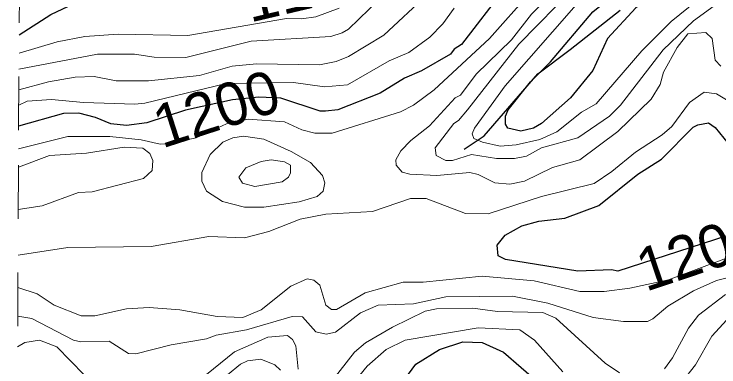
# Model space of a CAD drawing. Extents: x 577 to 602.9, y 7483.8 to 7511.6.
# Drawn here: x 577.007 to 578.319, y 7485.181 to 7485.838 of the extents above; entities that cross this region are included whole.
import ezdxf
from ezdxf.enums import TextEntityAlignment as Align

# ---------------------------------------------------------------- set-up
doc = ezdxf.new("R2010")
doc.units = 0
doc.header["$LTSCALE"] = 0.032
doc.linetypes.add('SHORT_DASHED', pattern=[2.7, 1.5, -1.2])
for name, color, linetype, lineweight in [('1', 7, 'Continuous', 25), ('2', 7, 'Continuous', 13), ('26', 7, 'Continuous', 25), ('62', 7, 'SHORT_DASHED', 13)]:
    doc.layers.add(name, color=color, linetype=linetype, lineweight=lineweight)
doc.layers.add('61', color=7, linetype='Continuous')

msp = doc.modelspace()

# ---------------------------------------------------------------- linework, layer by layer
at = {"layer": '1'}
msp.add_lwpolyline([(578.0846, 7485.8417), (578.1811, 7485.9204), (578.2654, 7486.0087), (578.2789, 7486.0166), (578.3051, 7486.019), (578.3258, 7486.0023), (578.329, 7485.9904), (578.3179, 7485.9578), (578.2853, 7485.9156), (578.2582, 7485.8973), (578.2193, 7485.891), (578.1644, 7485.8496), (578.1119, 7485.7924), (578.0841, 7485.7327), (578.0427, 7485.6818), (577.9887, 7485.6341), (577.9736, 7485.6254), (577.9505, 7485.6198), (577.9258, 7485.6254), (577.9219, 7485.6325), (577.9219, 7485.6476), (577.9266, 7485.6596), (577.968, 7485.7113), (578.0054, 7485.7486)], close=True, dxfattribs=at)
for points in [[(577.9211, 7485.887), (577.84, 7485.7812), (577.8264, 7485.7725), (577.8193, 7485.7629), (577.7652, 7485.7319), (577.7334, 7485.7184), (577.6881, 7485.6906), (577.6094, 7485.6596), (577.5863, 7485.6572), (577.5768, 7485.6572), (577.5036, 7485.681), (577.4626, 7485.6829), (577.4133, 7485.6782), (577.3257, 7485.6585), (577.2538, 7485.6355)], [(577.0161, 7485.7992), (577.075, 7485.8369), (577.1394, 7485.8679)], [(578.1684, 7485.5395), (578.2121, 7485.5673), (578.2709, 7485.627), (578.2797, 7485.6317), (578.2996, 7485.6349), (578.3123, 7485.6262), (578.3362, 7485.5968), (578.3481, 7485.5904), (578.3695, 7485.5864), (578.3998, 7485.5864), (578.4244, 7485.5952), (578.5015, 7485.6365), (578.558, 7485.6548), (578.6264, 7485.6508), (578.6534, 7485.6643), (578.6701, 7485.6675), (578.6828, 7485.6659), (578.7059, 7485.6484), (578.7306, 7485.6381), (578.7655, 7485.6357), (578.8037, 7485.6397), (578.9301, 7485.6675), (579.0303, 7485.7391)], [(577.2538, 7485.6355), (577.2157, 7485.6301), (577.1871, 7485.6333), (577.1585, 7485.6453), (577.1275, 7485.6532), (577.099, 7485.6523), (577.0152, 7485.629)], [(579.0049, 7485.5761), (578.962, 7485.5737), (578.8109, 7485.5252), (578.7695, 7485.518), (578.6868, 7485.5188), (578.5691, 7485.4838), (578.5063, 7485.4775), (578.4236, 7485.4536), (578.131, 7485.359), (578.1191, 7485.3614), (578.0563, 7485.359), (577.9219, 7485.3805), (577.9083, 7485.3876), (577.906, 7485.4075), (577.9211, 7485.4258), (577.9521, 7485.4433), (577.9839, 7485.452), (578.0324, 7485.4576), (578.0952, 7485.4815), (578.1684, 7485.5395)], [(577.6626, 7485.06), (577.7549, 7485.1856), (577.7986, 7485.2127), (577.8423, 7485.227), (577.8781, 7485.2262), (577.9179, 7485.2079), (577.9839, 7485.1507)]]:
    msp.add_lwpolyline(points, dxfattribs=at)
at = {"layer": '2'}
for points in [[(578.0483, 7485.9156), (577.9704, 7485.8377), (577.933, 7485.79), (577.867, 7485.7256), (577.8376, 7485.6866), (577.828, 7485.6818), (577.7803, 7485.6294), (577.7453, 7485.6023), (577.727, 7485.5832), (577.7175, 7485.5665), (577.7183, 7485.5562), (577.7294, 7485.5435), (577.7437, 7485.5395), (577.7938, 7485.5371), (577.8551, 7485.5427), (577.871, 7485.5387), (577.902, 7485.5236), (577.9298, 7485.5212), (577.9569, 7485.5268), (578.0093, 7485.5522), (578.0602, 7485.5665), (578.131, 7485.619), (578.193, 7485.6794), (578.2097, 7485.7065), (578.2161, 7485.7295), (578.2415, 7485.7757), (578.2614, 7485.8011), (578.2948, 7485.8035), (578.3067, 7485.7924), (578.3123, 7485.7518), (578.3226, 7485.7407)], [(577.0158, 7485.735), (577.1617, 7485.7629), (577.2309, 7485.7629), (577.2674, 7485.7574), (577.3263, 7485.7566), (577.4479, 7485.7876), (577.5966, 7485.7963), (577.6173, 7485.8027), (577.6292, 7485.8099), (577.7064, 7485.8846)], [(578.3377, 7485.8735), (578.2717, 7485.825), (578.2153, 7485.7709), (578.1358, 7485.6683), (578.1151, 7485.6476), (578.0563, 7485.6071), (577.9887, 7485.5888), (577.9608, 7485.5729), (577.9386, 7485.5689), (577.9052, 7485.5689), (577.8583, 7485.5761), (577.8233, 7485.5649), (577.8105, 7485.5649), (577.7923, 7485.5745), (577.7907, 7485.5888), (577.8256, 7485.6341), (577.8344, 7485.6397), (577.8511, 7485.6596), (577.9465, 7485.782), (578.0515, 7485.8894)], [(577.9672, 7485.8774), (577.8916, 7485.7924), (577.7891, 7485.6969), (577.7501, 7485.6683), (577.7263, 7485.6556), (577.599, 7485.6158), (577.5664, 7485.6158), (577.5426, 7485.6222), (577.51, 7485.6373), (577.4425, 7485.6422), (577.4019, 7485.6332), (577.3457, 7485.6074), (577.2959, 7485.5966), (577.2788, 7485.5957), (577.2433, 7485.6035), (577.185, 7485.6099), (577.1068, 7485.6095), (577.015, 7485.587)], [(577.7763, 7485.8751), (577.6952, 7485.7987), (577.6292, 7485.759), (577.6062, 7485.7494), (577.5752, 7485.7431), (577.4583, 7485.7454), (577.413, 7485.7407), (577.3517, 7485.7232), (577.2571, 7485.7136), (577.1967, 7485.7136), (577.1561, 7485.7216), (577.1203, 7485.72), (577.071, 7485.7113), (577.0156, 7485.6964)], [(578.2948, 7485.8767), (578.2304, 7485.8242), (578.1755, 7485.7693), (578.0904, 7485.6707), (578.0634, 7485.6548), (578.0173, 7485.6182), (577.9855, 7485.6039), (577.9417, 7485.5944), (577.9115, 7485.592), (577.8789, 7485.5991), (577.863, 7485.6063), (577.8598, 7485.615), (577.8638, 7485.6254), (577.9211, 7485.7041), (578.0531, 7485.8552)], [(577.6117, 7485.8488), (577.5688, 7485.8329), (577.5418, 7485.8289), (577.5139, 7485.8297), (577.3303, 7485.7979), (577.2006, 7485.8003), (577.1386, 7485.7963), (577.0869, 7485.786), (577.0159, 7485.7647)], [(577.8264, 7485.8488), (577.805, 7485.8194), (577.7811, 7485.7947), (577.7414, 7485.7661), (577.7048, 7485.751), (577.6277, 7485.7057), (577.5847, 7485.7025), (577.5267, 7485.7105)], [(577.5267, 7485.7105), (577.4018, 7485.7084), (577.2499, 7485.6717), (577.2318, 7485.6697), (577.1362, 7485.6731), (577.0766, 7485.6787), (577.031, 7485.6754), (577.0154, 7485.6681)], [(577.014, 7485.3887), (577.1068, 7485.4027), (577.2619, 7485.4051), (577.3692, 7485.4234), (577.436, 7485.421), (577.4813, 7485.4329), (577.5394, 7485.456), (577.5871, 7485.4648), (577.6738, 7485.4703), (577.7445, 7485.4942), (577.774, 7485.4942), (577.8471, 7485.4663), (577.8893, 7485.4655), (577.9887, 7485.4981), (578.0865, 7485.522), (578.1199, 7485.5443), (578.1636, 7485.5808), (578.2137, 7485.6127), (578.2312, 7485.6286), (578.2646, 7485.6731), (578.2916, 7485.6922), (578.3147, 7485.689), (578.36, 7485.662)], [(577.0149, 7485.5528), (577.0726, 7485.5745), (577.1418, 7485.5785), (577.2118, 7485.5901), (577.2466, 7485.588), (577.2594, 7485.578), (577.2651, 7485.5649), (577.2635, 7485.5467), (577.2476, 7485.5315), (577.1521, 7485.5069), (577.1267, 7485.5053), (577.0591, 7485.4807), (577.0145, 7485.4739)], [(578.3432, 7485.3866), (578.2252, 7485.3425), (578.1533, 7485.3272), (578.1056, 7485.3208), (578.0602, 7485.3208), (577.9751, 7485.3407), (577.8781, 7485.3495), (577.7684, 7485.3383), (577.731, 7485.3383), (577.6603, 7485.3184), (577.607, 7485.2874), (577.5974, 7485.2874), (577.5871, 7485.2954), (577.576, 7485.3328), (577.5648, 7485.3423)], [(577.0135, 7485.2752), (577.04, 7485.2707), (577.1171, 7485.2302), (577.1307, 7485.227), (577.1839, 7485.2286), (577.2197, 7485.2055), (577.2332, 7485.2047), (577.2992, 7485.2214), (577.3652, 7485.2326), (577.3827, 7485.2397), (577.4392, 7485.2493), (577.5243, 7485.2747), (577.5434, 7485.2739), (577.5688, 7485.2461), (577.5879, 7485.2413), (577.6054, 7485.2453), (577.6515, 7485.2811), (577.6849, 7485.2954), (577.7501, 7485.2978), (577.8105, 7485.3113), (577.9346, 7485.3121), (578.0006, 7485.2994), (578.0849, 7485.2723), (578.1413, 7485.2652), (578.1859, 7485.2652), (578.1962, 7485.2699), (578.224, 7485.2938), (578.2717, 7485.3224), (578.3147, 7485.3415), (578.3862, 7485.3598)], [(577.5648, 7485.3423), (577.5521, 7485.3447), (577.5219, 7485.3312), (577.467, 7485.2866), (577.4328, 7485.2723), (577.3851, 7485.2747), (577.3151, 7485.2866), (577.2579, 7485.2914), (577.2157, 7485.289), (577.1569, 7485.2755), (577.1315, 7485.2755), (577.0814, 7485.2954), (577.0496, 7485.3168), (577.0137, 7485.3287)], [(578.3314, 7485.3153), (578.2813, 7485.2771), (578.2622, 7485.2524), (578.2328, 7485.1976), (578.2177, 7485.1769)], [(578.1342, 7485.1697), (578.1071, 7485.1872), (578.0157, 7485.2715), (577.991, 7485.2819), (577.9068, 7485.2835), (577.8606, 7485.2898), (577.793, 7485.289), (577.7724, 7485.2842), (577.7111, 7485.2548), (577.661, 7485.2254), (577.6404, 7485.2079), (577.5831, 7485.134)], [(578.2503, 7485.1522), (578.2757, 7485.1841), (578.3059, 7485.2381), (578.3338, 7485.2683)], [(577.6507, 7485.165), (577.6642, 7485.1817), (577.6992, 7485.2127), (577.735, 7485.2302), (577.871, 7485.2532), (577.9481, 7485.2493), (577.9759, 7485.2302), (578.0284, 7485.1713)], [(577.5354, 7485.1761), (577.5314, 7485.2198), (577.5251, 7485.2318), (577.5155, 7485.2389), (577.479, 7485.2357), (577.4169, 7485.2087), (577.3652, 7485.1666)], [(577.0861, 7485.2182), (577.0543, 7485.2302), (577.027, 7485.2261), (577.0132, 7485.2181)], [(577.137, 7485.1658), (577.0861, 7485.2182)], [(577.4042, 7485.1658), (577.4281, 7485.1856), (577.4416, 7485.192), (577.4662, 7485.1952), (577.4925, 7485.1841), (577.5028, 7485.1745)]]:
    msp.add_lwpolyline(points, dxfattribs=at)
for points in [[(577.5227, 7485.5816), (577.5585, 7485.561), (577.5807, 7485.5371), (577.5855, 7485.5236), (577.5823, 7485.5077), (577.5712, 7485.4981), (577.5378, 7485.4878), (577.4718, 7485.4783), (577.436, 7485.4783), (577.3947, 7485.4886), (577.3652, 7485.5077), (577.3565, 7485.5268), (577.3565, 7485.5427), (577.3716, 7485.5761), (577.3955, 7485.5991), (577.4137, 7485.6071), (577.4336, 7485.6103), (577.4718, 7485.6047)], [(577.467, 7485.5634), (577.4853, 7485.5665), (577.51, 7485.5626), (577.5211, 7485.5562), (577.5211, 7485.5419), (577.5179, 7485.5339), (577.506, 7485.5252), (577.4551, 7485.5164), (577.432, 7485.5228), (577.4249, 7485.5339), (577.4384, 7485.5514)]]:
    msp.add_lwpolyline(points, close=True, dxfattribs=at)
at = {"layer": '26'}
msp.add_lwpolyline([(577.8448, 7485.5864), (577.882, 7485.6107), (577.982, 7485.7264), (578.042, 7485.7721), (578.1349, 7485.845)], dxfattribs=at)
at = {"layer": '62'}
msp.add_lwpolyline([(577.0067, 7483.927), (577.0095, 7484.4918), (577.0124, 7485.0566), (577.0152, 7485.6214), (577.0181, 7486.1863), (577.0209, 7486.7511), (577.0238, 7487.3159), (577.0267, 7487.8807), (577.0295, 7488.4455), (577.0324, 7489.0103), (577.0352, 7489.5752), (577.0381, 7490.14), (577.0409, 7490.7048), (577.0438, 7491.2696), (577.0466, 7491.8344), (577.0495, 7492.3992), (577.0523, 7492.9641)], dxfattribs=at)

# ---------------------------------------------------------------- texts
at = {"layer": '61', "width": 1.05}
msp.add_text('1100', height=0.08, rotation=13.324, dxfattribs=at).set_placement((577.5673, 7485.8505), align=Align.CENTER)
at = {"layer": '61'}
for rotation, p in [(17.835, (577.3955, 7485.6236)), (18.552, (578.2957, 7485.358))]:
    msp.add_text('1200', height=0.08, rotation=rotation, dxfattribs=at).set_placement(p, align=Align.CENTER)

doc.saveas('drawing.dxf')
